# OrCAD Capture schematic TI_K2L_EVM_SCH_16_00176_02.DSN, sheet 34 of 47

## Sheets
34 PAGE44 : K2L_POWER SECTION 3: size C; title: LM26430, 12v -> CVVD1, 1v8, v85, 5v
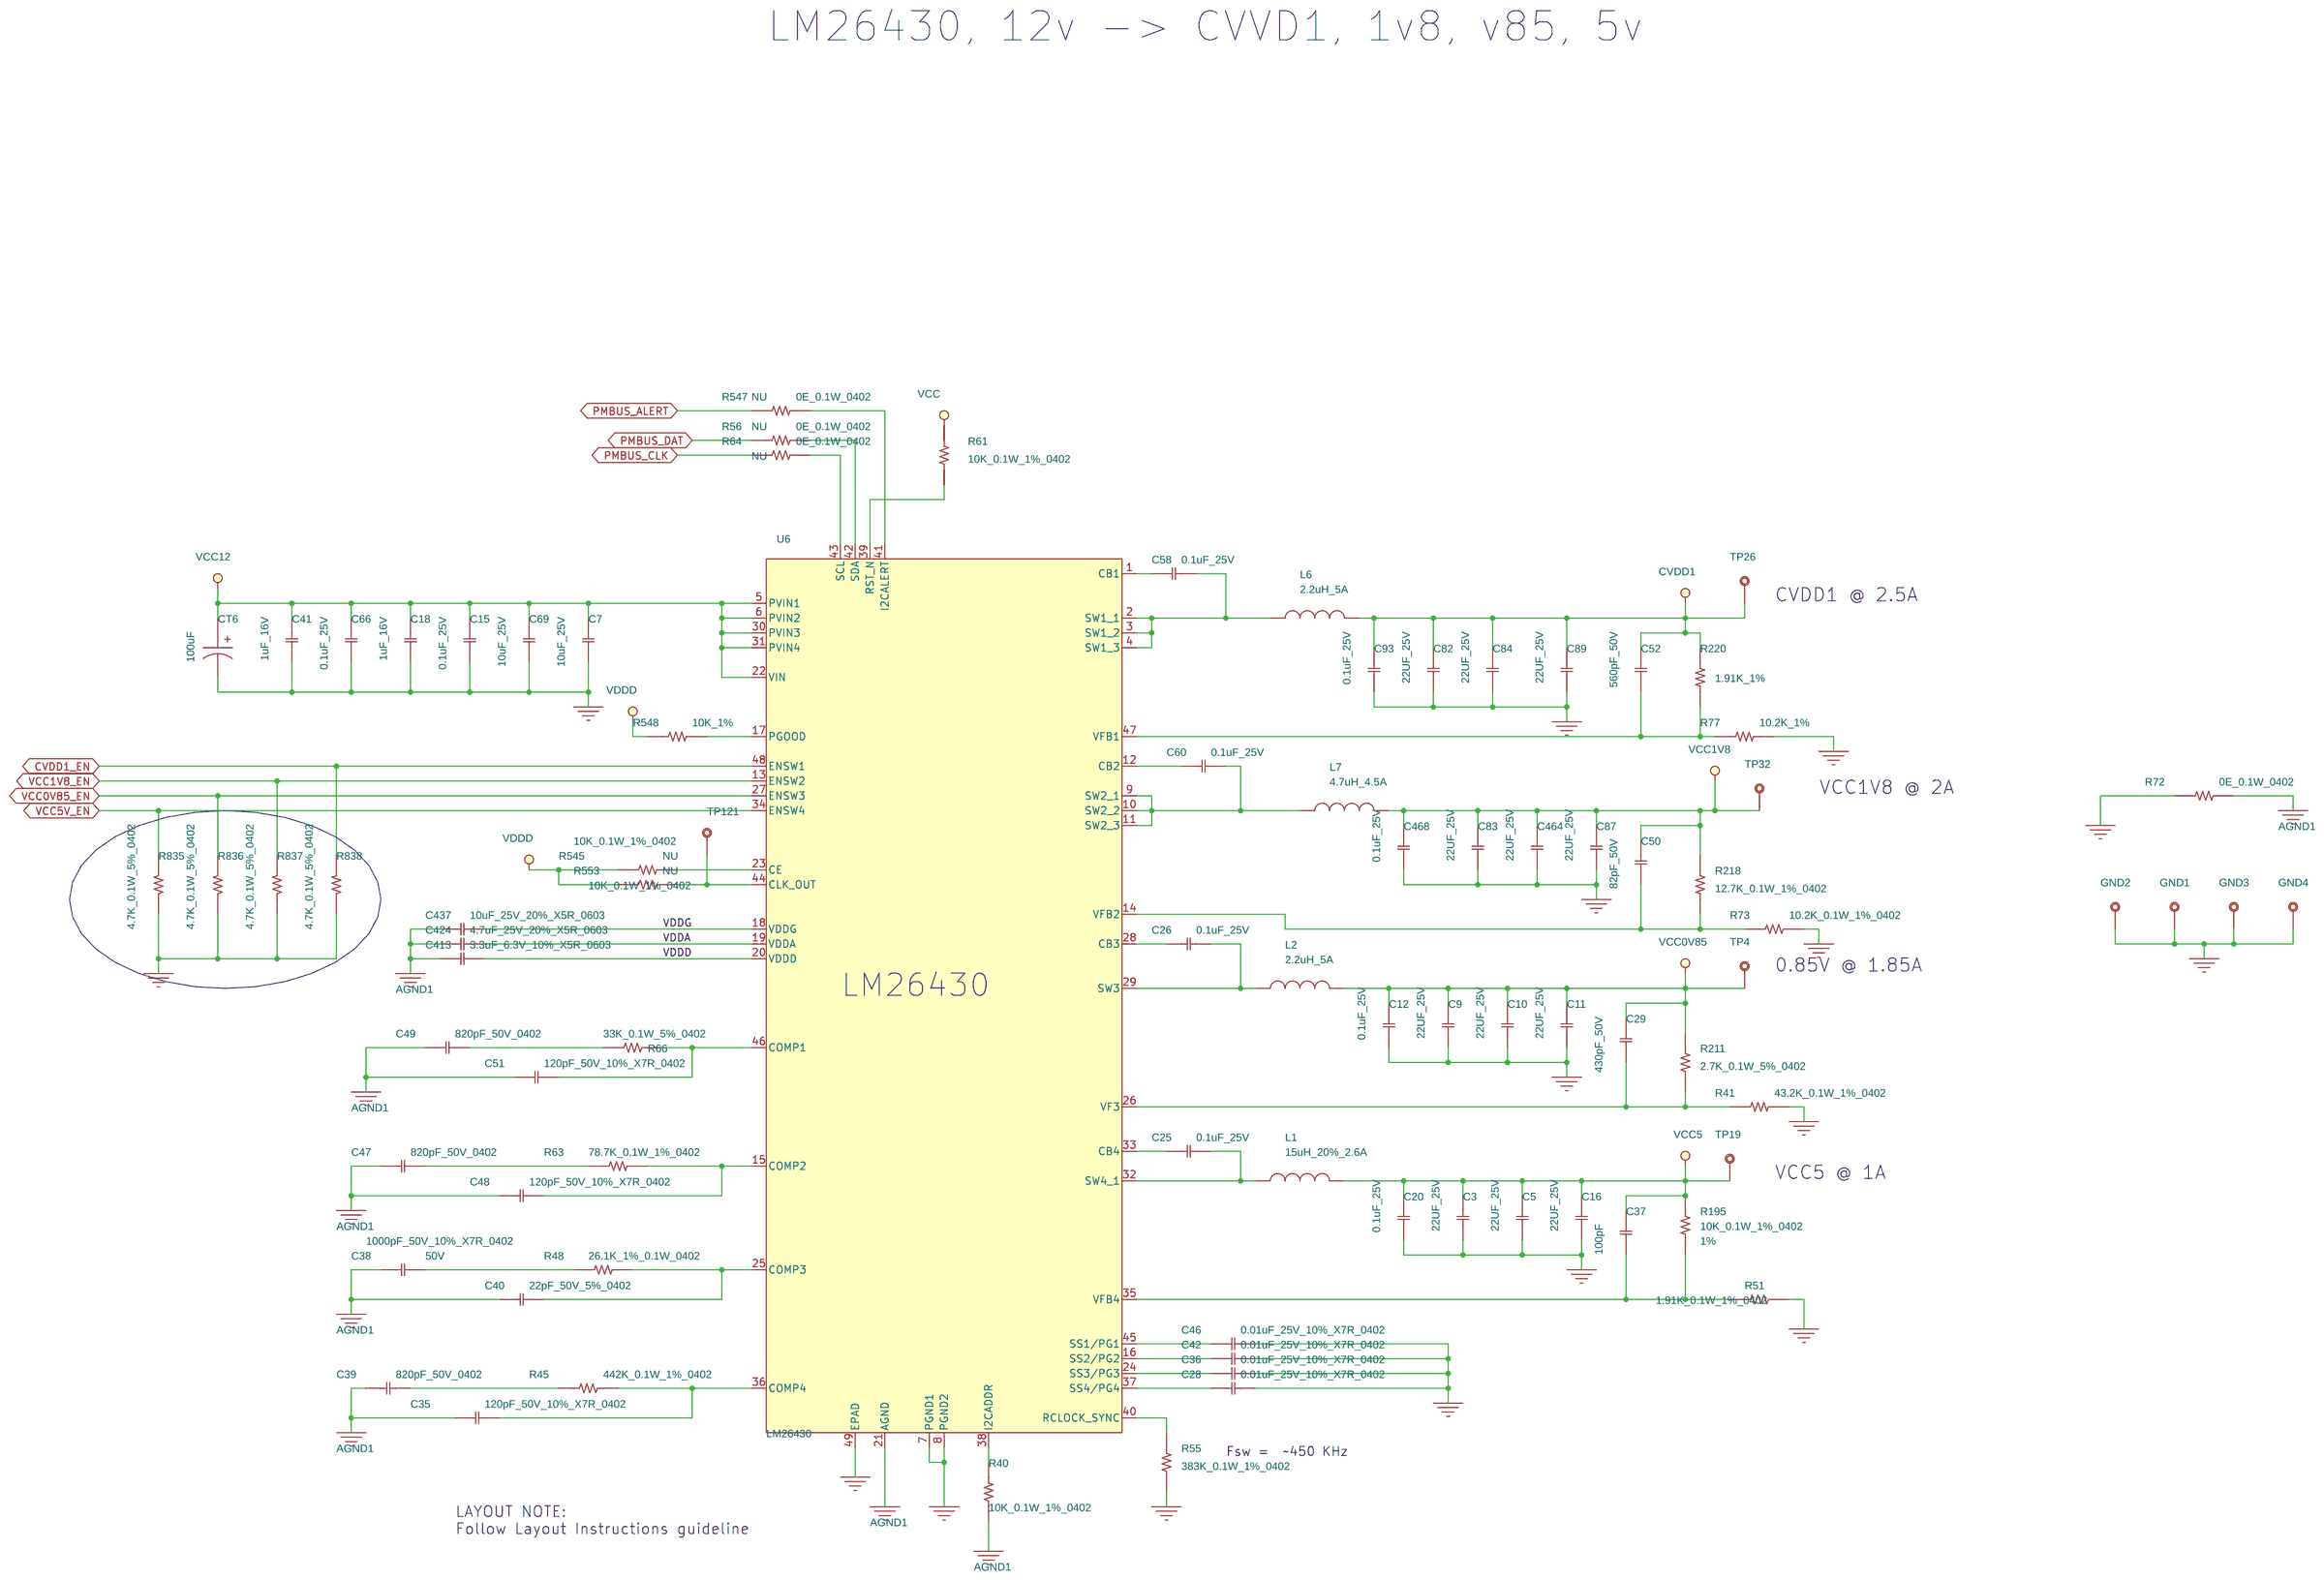
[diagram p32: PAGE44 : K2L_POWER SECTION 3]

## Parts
C3  22UF_25V  [C0805]
C5  22UF_25V  [C0805]
C7  10uF_25V  [C0603]
C9  22UF_25V  [C0805]
C10  22UF_25V  [C0805]
C11  22UF_25V  [C0805]
C12  0.1uF_25V  [C0402]
C15  0.1uF_25V  [C0402]
C16  22UF_25V  [C0805]
C18  1uF_16V  [C0402]
C20  0.1uF_25V  [C0402]
C25  0.1uF_25V  [C0402]
C26  0.1uF_25V  [C0402]
C28  0.01uF_25V_10%_X7R_0402  [C0402]
C29  430pF_50V  [C0402]
C35  120pF_50V_10%_X7R_0402  [C0402]
C36  0.01uF_25V_10%_X7R_0402  [C0402]
C37  100pF  [C0402]
C38  1000pF_50V_10%_X7R_0402  [C0402]
C39  820pF_50V_0402  [C0402]
C40  22pF_50V_5%_0402  [C0402]
C41  1uF_16V  [C0402]
C42  0.01uF_25V_10%_X7R_0402  [C0402]
C46  0.01uF_25V_10%_X7R_0402  [C0402]
C47  820pF_50V_0402  [C0402]
C48  120pF_50V_10%_X7R_0402  [C0402]
C49  820pF_50V_0402  [C0402]
C50  82pF_50V  [C0402]
C51  120pF_50V_10%_X7R_0402  [C0402]
C52  560pF_50V  [C0402]
C58  0.1uF_25V  [C0402]
C60  0.1uF_25V  [C0402]
C66  0.1uF_25V  [C0402]
C69  10uF_25V  [C0603]
C82  22UF_25V  [C0805]
C83  22UF_25V  [C0805]
C84  22UF_25V  [C0805]
C87  22UF_25V  [C0805]
C89  22UF_25V  [C0805]
C93  0.1uF_25V  [C0402]
C413  3.3uF_6.3V_10%_X5R_0603  [C0603]
C424  4.7uF_25V_20%_X5R_0603  [C0603]
C437  10uF_25V_20%_X5R_0603  [C0603]
C464  22UF_25V  [C0805]
C468  0.1uF_25V  [C0402]
CT6  100uF  [CT7343]
GND1  TP  [TP-S40]
GND2  TP  [TP-S40]
GND3  TP  [TP-S40]
GND4  TP  [TP-S40]
L1  15uH_20%_2.6A  [IND_ASPI-8040S-150M-T]
L2  2.2uH_5A  [IND_VLC5045T-2R2N]
L6  2.2uH_5A  [IND_VLC5045T-2R2N]
L7  4.7uH_4.5A  [IND_IHLP2020CZ]
R40  10K_0.1W_1%_0402  [R0402]
R41  43.2K_0.1W_1%_0402  [R0402]
R45  442K_0.1W_1%_0402  [R0402]
R48  26.1K_1%_0.1W_0402  [R0402]
R51  1.91K_0.1W_1%_0402  [R0402]
R55  383K_0.1W_1%_0402  [R0402]
R56  0E_0.1W_0402  [R0402]
R61  10K_0.1W_1%_0402  [R0402]
R63  78.7K_0.1W_1%_0402  [R0402]
R64  0E_0.1W_0402  [R0402]
R66  33K_0.1W_5%_0402  [R0402]
R72  0E_0.1W_0402  [R0402]
R73  10.2K_0.1W_1%_0402  [R0402]
R77  10.2K_1%  [R0402]
R195  10K_0.1W_1%_0402  [R0402]
R211  2.7K_0.1W_5%_0402  [R0402]
R218  12.7K_0.1W_1%_0402  [R0402]
R220  1.91K_1%  [R0402]
R545  10K_0.1W_1%_0402  [R0402]
R547  0E_0.1W_0402  [R0402]
R548  10K_1%  [R0402]
R553  10K_0.1W_1%_0402  [R0402]
R835  4.7K_0.1W_5%_0402  [R0402]
R836  4.7K_0.1W_5%_0402  [R0402]
R837  4.7K_0.1W_5%_0402  [R0402]
R838  4.7K_0.1W_5%_0402  [R0402]
TP4  TP  [TP-S40]
TP19  TP  [TP-S40]
TP26  TP  [TP-S40]
TP32  TP  [TP-S40]
TP121  TP  [TP-S40]
U6  LM26430  [QFN50P700X700X100-49N_C_EINF]

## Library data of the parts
C3 C5 C9-C11 C16 C82-C84 C87 C89 C464 = 11_C_0: CAP CER 22UF 25V 20% JB 0805; Alternate_Mfr: Samsung; Alternate_Partno: CL21A226MAQNNNE; Distributor_name: DIGIKEY; Distributor_part_number: 445-11475-2-ND; EIC Part#: 03_00586_01; Manufacture: TDK Corporation; Manufacture Part Number: C2012JB1E226M125AC; Manufacture(English): TDK Corporation; Manufacture_Part_Number: C2012JB1E226M125AC; Manufacturer: TDK Corporation; Manufacturer_Part_No: C2012JB1E226M125AC; Mfg: TDK Corporation; Mfg Part#: C2012JB1E226M125AC; Mfr_name: TDK Corporation; Mfr_part_number: C2012JB1E226M125AC; Oper. Temp. Range: -55C to 85C; Package: 0805; Price @ 1: 1.09000; Price @ 10K: 0.26265; Price @ 1K: 0.37647; ProcessType: SMT; RoHS: Yes; Tolerance: 10%; Vendor: DIGIKEY; Vendor Part#: 490-5527-1-ND; Vendor_Part_No: 03_00586_01; Voltage: 25V; eI Part#: 03_00586_01
C7 C69 = 11_C_12: CAP CER 10UF 25V 20% X5R 0603; Characteristic: <Characteristic>; Distributor_name: DIGIKEY; Distributor_part_number: 445-9015-1-ND; EIC Part#: 03_00609_01; Manufacture: TDK Corporation; Manufacture Part Number: C1608X5R1E106M080AC; Manufacture(English): TDK Corporation; Manufacture_Part_Number: C1608X5R1E106M080AC; Manufacturer: TDK Corporation; Manufacturer_Part_No: C1608X5R1E106M080AC; Mfg: TDK Corporation; Mfg Part#: C1608X5R1E106M080AC; Mfr_name: TDK Corporation; Mfr_part_number: C1608X5R1E106M080AC; Oper. Temp. Range: -55C to 85C; Package: 0603; Price @ 1: 0.60000; Price @ 10K: 0.19125; Price @ 1K: 0.19125; ProcessType: SMT; RoHS: Yes; Tolerance: 20%; Vendor: DIGIKEY; Vendor Part#: TDK Corporation; Vendor_Part_No: 445-9015-1-ND; Voltage: 25V; eI Part#: 03_00609_01
C12 C15 C20 C25 C26 C58 C60 C66 C93 C468 = 11_C_0: CAP CER 0.1UF 25V 10% X5R 0402; Alt Mfg: Taiyo Yuden; Distributor_name: DIGIKEY; Distributor_part_number: 445-4964-1-ND; EIC Part#: 03_00470_02; Manufacture: TDK Corporation; Manufacture Part Number: C1005X5R1E104K050BC; Manufacture(English): TDK Corporation; Manufacture_Part_Number: GRM155R61E104KA87D; Manufacturer: TDK Corporation; Manufacturer_Part_No: C1005X5R1E104K050BC; Mfg: Murata Electronics North America; Mfg Part#: 03_00470_02; Mfr_name: TDK Corporation; Mfr_part_number: C1005X5R1E104K050BC; Oper. Temp. Range: -55°C ~ 85°C; Package: 0402; Price @ 1: 0.10000; Price @ 1K: 0.00960; ProcessType: SMT; RoHS: Yes; Tolerance: 10%; Vendor: DIGIKEY; Vendor Part#: 445-4964-1-ND; Vendor_Part_No: 445-4964-1-ND; eI Part#: 03_00470_02
C18 C41 = 11_C_12: CAP CER 1UF 16V 10% X5R 0402; Characteristic: <Characteristic>; Distributor_name: DIGIKEY; Distributor_part_number: 445-4978-1-ND; EIC Part#: 03_00355_04; Manufacture: TDK Corporation; Manufacture Part Number: C1005X5R1C105K050BC; Manufacture(English): TDK Corporation; Manufacture_Part_Number: C1005X5R1C105K050BC; Manufacturer: TDK Corporation; Manufacturer_Part_No: C1005X5R1C105K050BC; Mfg: TDK Corporation; Mfg Part#: C1005X5R1C105K050BC; Mfr_name: TDK Corporation; Mfr_part_number: C1005X5R1C105K050BC; Oper. Temp. Range: -55C to 85C; Package: 0402; Price @ 1: 0.12000; Price @ 10K: 0.01600; Price @ 1K: 0.02200; ProcessType: SMT; RoHS: Yes; Tolerance: 10%; Vendor: DIGIKEY; Vendor Part#: 445-4978-1-ND; Vendor_Part_No: 445-4978-1-ND; Voltage: 25V; eI Part#: 03_00355_04
C28 C36 C42 C46 = 11_C_0: CAP CER 10000PF 25V 10% X7R 0402; Alt Mfg: Murata; Alt Mfg Part#: GRM155R71C103KA01D; Distributor_name: DIGIKEY; Distributor_part_number: 445-1260-1-ND; EIC Part#: 03_00029_04; Manufacture: TDK Corporation; Manufacture Part Number: C1005X7R1E103K; Manufacture(English): TDK Corporation; Manufacture_Part_Number: C1005X7R1E103K; Manufacturer: TDK Corporation; Manufacturer_Part_No: C1005X7R1E103K; Mfg: TDK Corporation; Mfg Part#: 03_00029_04; Mfr_name: TDK Corporation; Mfr_part_number: C1005X7R1E103K; Oper. Temp. Range: -55C to 125C; Package: 0402; Price @ 1: 0.10000; Price @ 10K: 0.00420; Price @ 1K: 0.00600; ProcessType: SMT; RoHS: Yes; Tolerance: 10%; Vendor: DIGIKEY; Vendor Part#: PCC103BQCT-ND; Vendor_Part_No: 445-1260-1-ND; eI Part#: 03_00029_04
C29 = 11_C_0: CAP CER 430PF 50V 2% NP0 0402; Distributor_name: DIGIKEY; Distributor_part_number: 490-6240-1-ND; EIC Part#: TBD; Manufacture: Murata; Manufacture Part Number: GRM1555C1H431GA01D; Manufacture(English): Murata; Manufacture_Part_Number: GRM1555C1H431GA01D; Manufacturer: Murata; Manufacturer_Part_No: GRM1555C1H431GA01D; Mfg Part#: TBD; Mfr_name: Murata; Mfr_part_number: GRM1555C1H431GA01D; Oper. Temp. Range: -55C to 125C; Package: 0402; ProcessType: SMT; RoHS: Yes; Tolerance: 10%; Vendor: DIGIKEY; Vendor Part#: 490-6240-1-ND; Vendor_Part_No: 490-6240-1-ND; Voltage: 50V; eI Part#: TBD
C35 C48 C51 = 11_C_0: CAP CER 120PF 10% 50V X7R 0402; Distributor_name: DIGIKEY; Distributor_part_number: 478-1090-1-ND; EIC Part#: 03_00049_03; Manufacture: AVX Corporation; Manufacture Part Number: 04025C121KAT2A; Manufacture(English): AVX Corporation; Manufacture_Part_Number: 04025C121KAT2A; Manufacturer: AVX Corporation; Manufacturer_Part_No: 04025C121KAT2A; Mfg: AVX Corporation; Mfg Part#: 03_00049_03; Mfr_name: AVX Corporation; Mfr_part_number: 04025C121KAT2A; Oper. Temp. Range: -55C to 125C; Package: 0402; Price @ 1: 0.12000; Price @ 10K: 0.01470; Price @ 1K: 0.02100; ProcessType: SMT; RoHS: Yes; Tolerance: 10%; Vendor: DIGIKEY; Vendor Part#: 478-1090-1-ND; Vendor_Part_No: 478-1090-1-ND; Voltage: 50V; eI Part#: 03_00049_03
C37 = 11_C_12: CAP CER 100PF 50V 5% NP0 0402; Characteristic: <Characteristic>; Distributor_name: DIGIKEY; Distributor_part_number: 490-5922-1-ND; EIC Part#: 03_00594_01; Manufacture: Murata; Manufacture Part Number: GRM1555C1H101JA01D; Manufacture(English): 490-5922-1-ND; Manufacture_Part_Number: GRM1555C1H101JA01D; Manufacturer: Murata; Manufacturer_Part_No: GRM1555C1H101JA01D; Mfg: Murata; Mfg Part#: GRM1555C1H101JA01D; Mfr_name: Murata; Mfr_part_number: GRM1555C1H101JA01D; Oper. Temp. Range: -55°C ~ 125°C; Package: 0402; Price @ 1: 0.10000; Price @ 10K: 0.00500; Price @ 1K: 0.00600; ProcessType: SMT; RoHS: Yes; Tolerance: 5%; Vendor: DIGIKEY; Vendor Part#: 490-5922-1-ND; Vendor_Part_No: 490-5922-1-ND; Voltage: 50V; eI Part#: 03_00594_01
C38 = 11_C_0: CAP CER 1000PF 50V 10% X7R 0402; Advansus_Part_Number: 11G232110214030; Characteristic: 50V; Distributor_name: DIGIKEY; Distributor_part_number: 1276-1493-1-ND; EIC Part#: 03_00591_01; Manufacture: Samsung; Manufacture Part Number: CL05B102KB5NFNC; Manufacture(English): Samsung; Manufacture_Part_Number: CL05B102KB5NFNC; Manufacturer: Samsung; Manufacturer_Part_No: CL05B102KB5NFNC; Mfg: Samsung; Mfg Part#: CL05B102KB5NFNC; Mfr_name: Samsung; Mfr_part_number: CL05B102KB5NFNC; Package: 0402; Part_Number: 1124510291; Price @ 1: 0.10000; Price @ 10K: 0.00216; Price @ 1K: 0.00309; ProcessType: SMT; Tolerance: 10%; Vendor: DIGIKEY; Vendor Part#: 1276-1493-1-ND; Vendor_Part_No: 1276-1493-1-ND; eI Part#: 03_00591_01
C39 C47 C49 = 11_C_12: CAP CER 820PF 50V 10% X7R 0402; Characteristic: 50V; Distributor_name: DIGIKEY; Distributor_part_number: 490-3250-1-ND; EIC Part#: 03_00285_02; Manufacture: Murata; Manufacture Part Number: GRM155R71H821KA01D; Manufacture(English): Murata; Manufacture_Part_Number: GRM155R71H821KA01D; Manufacturer: Murata; Manufacturer_Part_No: GRM155R71H821KA01D; Mfg: Murata Electronics North America; Mfg Part#: 03_00285_02; Mfr_name: Murata; Mfr_part_number: GRM155R71H821KA01D; Oper. Temp. Range: -55°C ~ 125°C; Package: 0402; Price @ 1: 0.10000; Price @ 10K: 0.00441; Price @ 1K: 0.00630; ProcessType: SMT; RoHS: Yes; Tolerance: 10%; Vendor: DIGIKEY; Vendor Part#: 490-1301-1-ND; Vendor_Part_No: 490-3250-1-ND; Voltage: 50V; eI Part#: 03_00285_02
C40 = 11_C_0: CAP CER 22PF 50V 0402 SMD; Alt Mfg: Yageo; Alt Mfg Part#: CC0402JRNPO9BN220; Alternate_Mfr: TDK Corporation; Alternate_Partno: C1005C0G1H220J050BA; Distributor_name: DIGIKEY; Distributor_part_number: PCC220CQCT-ND; EIC Part#: 03_00204_02; Manufacture: Panasonic - ECG; Manufacture Part Number: ECJ-0EC1H220J; Manufacture(English): Panasonic - ECG; Manufacture_Part_Number: ECJ-0EC1H220J; Manufacturer: Panasonic - ECG; Manufacturer_Part_No: ECJ-0EC1H220J; Mfg: Panasonic - ECG; Mfg Part#: 03_00204_02; Mfr_name: Panasonic - ECG; Mfr_part_number: ECJ-0EC1H220J; Oper. Temp. Range: -55C to 125C; Package: 0402; Price @ 1: TBD; Price @ 10K: TBD; Price @ 1K: TBD; ProcessType: SMT; RoHS: Yes; Tolerance: 5%; Vendor: DIGIKEY; Vendor Part#: PCC220CQCT-ND; Vendor_Part_No: PCC220CQCT-ND; eI Part#: 03_00204_02
C50 = 11_C_0: CAP CER 82PF 50V 5% NP0 0402; Distributor_name: DIGIKEY; Distributor_part_number: 490-5879-1-ND; EIC Part#: 03_00598_01; Manufacture: Murata; Manufacture Part Number: GRM1555C1H820JA01D; Manufacture(English): Murata; Manufacture_Part_Number: GRM1555C1H820JA01D; Manufacturer: Murata; Manufacturer_Part_No: GRM1555C1H820JA01D; Mfg: Murata Electronics North America; Mfg Part#: 03_00598_01; Mfr_name: Murata; Mfr_part_number: GRM1555C1H820JA01D; Oper. Temp. Range: -55C to 125C; Package: 0402; Price @ 1: 0.10000; Price @ 10K: 0.00368; Price @ 1K: 0.00525; ProcessType: SMT; RoHS: Yes; Tolerance: 10%; Vendor: DIGIKEY; Vendor Part#: 490-5879-1-ND; Vendor_Part_No: 490-5879-1-ND; Voltage: 50V; eI Part#: 03_00598_01
C52 = 11_C_12: CAP CER 560PF 50V 10% X7R 0402; Avalue_Part_Number: E1127556100H; Characteristic: 50V; Distributor_name: DIGIKEY; Distributor_part_number: 490-1301-1-ND; EIC Part#: 03_00189_02; Manufacture: Murata; Manufacture Part Number: GRM155R71H561KA01D; Manufacture(English): Murata; Manufacture_Part_Number: GRM155R71H561KA01D; Manufacturer: Murata; Manufacturer_Part_No: GRM155R71H561KA01D; Mfg: Murata Electronics North America; Mfg Part#: 03_00189_02; Mfr_name: Murata; Mfr_part_number: GRM155R71H561KA01D; Oper. Temp. Range: -55°C ~ 125°C; Package: 0402; Price @ 1: 0.10000; Price @ 10K: 0.00672; Price @ 1K: 0.00960; ProcessType: SMT; RoHS: Yes; Tolerance: 10%; Vendor: DIGIKEY; Vendor Part#: 490-1301-1-ND; Vendor_Part_No: 490-1301-1-ND; Voltage: 50V; eI Part#: 03_00189_02
C413 = 11_C_0: CAP CER 3.3UF 6.3V 10% X5R 0603; Distributor_name: DIGIKEY; Distributor_part_number: 445-5176-1-ND; EIC Part#: 03_00585_01; Manufacture: TDK Corporation; Manufacture Part Number: C1608X5R0J335K080AB; Manufacture(English): TDK Corporation; Manufacture_Part_Number: C1608X5R0J335K080AB; Manufacturer: TDK Corporation; Manufacturer_Part_No: C1608X5R0J335K080AB; Mfg: TDK Corporation; Mfg Part#: 03_00585_01; Mfr_name: TDK Corporation; Mfr_part_number: C1608X5R0J335K080AB; Oper. Temp. Range: -55C to 85C; Package: 0603; Price @ 1: 0.24000; Price @ 10K: 0.04625; Price @ 1K: 0.05875; ProcessType: SMT; RoHS: Yes; Tolerance: 10%; Vendor: DIGIKEY; Vendor Part#: 445-5176-1-ND; Vendor_Part_No: 445-5176-1-ND; Voltage: 6.3V; eI Part#: 03_00585_01
C424 = 11_C_0: CAP CER 4.7UF 25V 20% X5R 0603; Distributor_name: DIGIKEY; Distributor_part_number: 1276-1903-2-ND; EIC Part#: 03_00592_01; Manufacture: Samsung; Manufacture Part Number: CL10A475MA8NQNC; Manufacture(English): Samsung; Manufacture_Part_Number: CL10A475MA8NQNC; Manufacturer: Samsung; Manufacturer_Part_No: CL10A475MA8NQNC; Mfg: Samsung; Mfg Part#: CL10A475MA8NQNC; Mfr_name: Samsung; Mfr_part_number: CL10A475MA8NQNC; Oper. Temp. Range: -55C to 85C; Package: 0603; ProcessType: SMT; RoHS: Yes; Tolerance: 10%; Vendor: DIGIKEY; Vendor Part#: 1276-1903-2-ND; Vendor_Part_No: 1276-1903-2-ND; Voltage: 25V; eI Part#: 03_00592_01
C437 = 11_C_0: CAP CER 10UF 25V 20% X5R 0603; Distributor_name: DIGIKEY; Distributor_part_number: 445-9015-1-ND; EIC Part#: 03_00609_01; Manufacture: TDK Corporation; Manufacture Part Number: C1608X5R1E106M080AC; Manufacture(English): TDK Corporation; Manufacture_Part_Number: C1608X5R1E106M080AC; Manufacturer: TDK Corporation; Manufacturer_Part_No: C1608X5R1E106M080AC; Mfg: TDK Corporation; Mfg Part#: C1608X5R1E106M080AC; Mfr_name: TDK Corporation; Mfr_part_number: C1608X5R1E106M080AC; Oper. Temp. Range: -55C to 85C; Package: 0603; Price @ 1: 0.60000; Price @ 10K: 0.19125; Price @ 1K: 0.19125; ProcessType: SMT; RoHS: Yes; Tolerance: 20%; Vendor: DIGIKEY; Vendor Part#: TDK Corporation; Vendor_Part_No: 445-9015-1-ND; Voltage: 25V; eI Part#: 03_00609_01
CT6 = CAP_POL: CAP TANT 100UF 20V 10% 2917; Distributor_name: DIGIKEY; Distributor_part_number: 718-1774-1-ND; EIC Part#: 03_00602_01; Manufacture: Vishay; Manufacture Part Number: TR3D107K020C0080; Manufacture(English): Vishay Dale; Manufacture_Part_Number: TR3D107K020C0080; Manufacturer: Vishay Dale; Manufacturer_Part_No: TR3D107K020C0080; Mfg: Vishay Dale; Mfg Part#: TR3D107K020C0080; Mfr_name: Vishay Dale; Mfr_part_number: TR3D107K020C0080; Oper. Temp. Range: -40°C ~ 85°C; Package: 7343; RoHS: Yes; Vendor: DIGIKEY; Vendor Part#: 718-1774-1-ND; Vendor_Part_No: 718-1774-1-ND; Voltage: 25V; eI Part#: 03_00602_01
GND1-GND4 TP4 TP19 TP26 TP32 TP121 = 00_TP-S40_0: TEST PAD TP; Distributor_name: NA; Distributor_part_number: NA; EIC Part#: NA; Manufacture: NA; Manufacture Part Number: NA; Manufacture(English): NA; Manufacture_Part_Number: NA; Manufacturer: NA; Manufacturer_Part_No: NA; Mfg: NA; Mfg Part#: NA; Mfr_name: NA; Mfr_part_number: NA; Oper. Temp. Range: --NA--; Package: --NA--; Price @ 1: NA; Price @ 10K: NA; Price @ 1K: NA; ProcessType: SMT; RoHS: Yes; Vendor: NA; Vendor Part#: --NA--; Vendor_Part_No: NA; eI Part#: NA
L1 = DISC_INDUCTOR: INDUCTOR POWER 15UH 20% SMD; Distributor_name: DIGIKEY; Distributor_part_number: ASPI-8040S-150M-TCT-ND; EIC Part#: TBD; Manufacture: Abracon Corporation; Manufacture Part Number: ASPI-8040S-150M-T; Manufacture(English): Abracon Corporation; Manufacture_Part_Number: ASPI-8040S-150M-T; Manufacturer: Abracon Corporation; Manufacturer_Part_No: ASPI-8040S-150M-T; Mfg: Abracon Corporation; Mfg Part#: TBD; Mfr_name: Abracon Corporation; Mfr_part_number: ASPI-8040S-150M-T; Price @ 1: 0.73000; Price @ 10K: 0.43876; Price @ 1K: 0.29250; RoHS: Yes; RoHS Compliant?: RoHS Compliant; Tolerance: 20%; Vendor: DIGIKEY; Vendor Part#: ASPI-8040S-150M-TCT-ND; Vendor_Part_No: ASPI-8040S-150M-TCT-ND; eI Part#: TBD
L2 L6 = DISC_INDUCTOR: INDUCTOR POWER 2.2UH 5.0A SMD; Distributor_name: DIGIKEY; Distributor_part_number: 445-6523-1-ND; EIC Part#: 04_00346_01; Manufacture: TDK Corporation; Manufacture Part Number: VLC5045T-2R2N; Manufacture(English): TDK Corporation; Manufacture_Part_Number: VLC5045T-2R2N; Manufacturer: TDK Corporation; Manufacturer_Part_No: VLC5045T-2R2N; Mfg Part#: VLC5045T-2R2N; Mfr_name: TDK Corporation; Mfr_part_number: VLC5045T-2R2N; Price @ 1: 0.48000; Price @ 10K: 0.13664; Price @ 1K: 0.16800; RoHS Compliant?: RoHS Compliant; Vendor: DIGIKEY; Vendor_Part_No: 445-6523-1-ND; eI Part#: 04_00408_01
L7 = DISC_INDUCTOR: INDUCTOR POWER 4.7UH 4.5A SMD; Distributor_name: DIGIKEY; Distributor_part_number: 541-1238-1-ND; EIC Part#: 04_00380_01; Manufacture: Vishay Dale; Manufacture Part Number: IHLP2020CZER4R7M11; Manufacture(English): Vishay Dale; Manufacture_Part_Number: IHLP2020CZER4R7M11; Manufacturer: Vishay Dale; Manufacturer_Part_No: IHLP2020CZER4R7M11; Mfg Part#: 04_00380_01; Mfr_name: Vishay Dale; Mfr_part_number: IHLP2020CZER4R7M11; Price @ 1: 2.40000; Price @ 10K: 0.99200; Price @ 1K: 1.31200; RoHS Compliant?: RoHS Compliant; Vendor: DIGIKEY; Vendor_Part_No: 541-1238-1-ND; eI Part#: 04_00380_01
R40 R61 R548 = 10_R_0: RES 10K OHM 1/10W 1% 0402 SMD; Alt Mfg: Yageo; Alt Mfg Part#: RC0402FR-0710KL; Distributor_name: DIGIKEY; Distributor_part_number: P10.0KLCT-ND; EIC Part#: 02_00027_01; Manufacture: Panasonic - ECG; Manufacture Part Number: ERJ-2RKF1002X; Manufacture(English): Panasonic - ECG; Manufacture_Part_Number: ERJ-2RKF1002X; Manufacturer: Panasonic - ECG; Manufacturer_Part_No: ERJ-2RKF1002X; Mfg Part#: 02_00027_01; Mfr_name: Panasonic - ECG; Mfr_part_number: ERJ-2RKF1002X; Oper. Temp. Range: -55C ~ 125C; Package: 0402; Price @ 1: 0.10000; Price @ 10K: 0.00347; Price @ 1K: 0.00672; ProcessType: SMT; Remark: Alt part is 1/16W; RoHS: Yes; Tolerance: 1%; Vendor: DIGIKEY; Vendor Part#: P10.0KLCT-ND; Vendor_Part_No: P10.0KLCT-ND; eI Part#: 02_00027_01
R41 = 10_R_0: RES 43.2K OHM 1/10W 1% 0402 SMD; Distributor_name: DIGIKEY; Distributor_part_number: P43.2KLCT-ND; EIC Part#: 02_00764_01; Manufacture: Panasonic - ECG; Manufacture Part Number: ERJ-2RKF4322X; Manufacture(English): Panasonic - ECG; Manufacture_Part_Number: ERJ-2RKF4322X; Manufacturer: Panasonic - ECG; Manufacturer_Part_No: ERJ-2RKF4322X; Mfg Part#: 02_00764_01; Mfr_name: Panasonic - ECG; Mfr_part_number: ERJ-2RKF4322X; Oper. Temp. Range: -55C ~ 125C; Package: 0402; ProcessType: SMT; RoHS: Yes; Tolerance: 1%; Vendor: DIGIKEY; Vendor Part#: P43.2KLCT-ND; Vendor_Part_No: P43.2KLCT-ND; eI Part#: 02_00024_01
R45 = 10_R_0: RES 442K OHM 1/16W 1% 0402 SMD; Distributor_name: DIGIKEY; Distributor_part_number: P442KLCT-ND; EIC Part#: 02_00308_01; Manufacture: Panasonic - ECG; Manufacture Part Number: ERJ-2RKF4423X; Manufacture(English): Panasonic - ECG; Manufacture_Part_Number: ERJ-2RKF4423X; Manufacturer: Panasonic - ECG; Manufacturer_Part_No: ERJ-2RKF4423X; Mfg Part#: 02_00308_01; Mfr_name: Panasonic - ECG; Mfr_part_number: ERJ-2RKF4423X; Oper. Temp. Range: ±100ppm/°C; Package: 0402; ProcessType: SMT; RoHS: Yes; Tolerance: 1%; Vendor: DIGIKEY; Vendor Part#: 541-442KLCT-ND; Vendor_Part_No: P442KLCT-ND; eI Part#: 02_00483_01
R48 = 10_R_0: RES 26.1K OHM 1/10W 1% 0402 SMD; Distributor_name: DIGIKEY; Distributor_part_number: TBD; EIC Part#: TBD; Manufacture: Panasonic - ECG; Manufacture Part Number: ERJ-2RKF2612X; Manufacture(English): Panasonic - ECG; Manufacture_Part_Number: ERJ-2RKF2612X; Manufacturer: Panasonic - ECG; Manufacturer_Part_No: ERJ-2RKF2612X; Mfg Part#: TBD; Mfr_name: Panasonic - ECG; Mfr_part_number: ERJ-2RKF2612X; Oper. Temp. Range: -55C ~ 125C; Package: 0402; ProcessType: SMT; Remark: Alt part is 1/10W; RoHS: Yes; Tolerance: 1%; Vendor: DIGIKEY; Vendor Part#: TBD; Vendor_Part_No: TBD; eI Part#: TBD
R51 R220 = 10_R_0: RES 1.91K OHM 1/10W 1% 0402 SMD; Alt Mfg: Yageo; Alt Mfg Part#: RC0402FR-0710KL; Distributor_name: DIGIKEY; Distributor_part_number: P1.91KLCT-ND; EIC Part#: 02_00297_02; Manufacture: Panasonic - ECG; Manufacture Part Number: ERJ-2RKF1911X; Manufacture(English): Panasonic - ECG; Manufacture_Part_Number: ERJ-2RKF1911X; Manufacturer: Panasonic - ECG; Manufacturer_Part_No: ERJ-2RKF1911X; Mfg Part#: 02_00297_02; Mfr_name: Panasonic - ECG; Mfr_part_number: ERJ-2RKF1911X; Oper. Temp. Range: -55C ~ 125C; Package: 0402; ProcessType: SMT; Remark: Alt part is 1/10W; RoHS: Yes; Tolerance: 1%; Vendor: DIGIKEY; Vendor Part#: P1.91KLDKR-ND; Vendor_Part_No: P1.91KLCT-ND; eI Part#: 02_00483_01
R55 = 10_R_0: RES 383K OHM 1/10W 1% 0402 SMD; Distributor_name: DIGIKEY; Distributor_part_number: P383KLCT-ND; EIC Part#: TBD; Manufacture: Panasonic - ECG; Manufacture Part Number: ERJ-2RKF3833X; Manufacture(English): Panasonic - ECG; Manufacturer: Panasonic - ECG; Manufacturer_Part_No: ERJ-2RKF3833X; Mfg Part#: TBD; Mfr_name: Panasonic - ECG; Mfr_part_number: ERJ-2RKF3833X; Oper. Temp. Range: -55C ~ 125C; Package: 0402; ProcessType: SMT; Remark: Alt part is 1/10W; RoHS: Yes; Tolerance: 1%; Vendor: DIGIKEY; Vendor_Part_No: P383KLCT-ND; eI Part#: 02_00027_01
R56 R64 R547 = 10_R_0: RES 0.0 OHM 1/10W JUMP 0402 SMD; Alt Mfg: Yageo; Distributor_name: DIGIKEY; Distributor_part_number: P0.0JCT-ND; EIC Part#: 02_00019_01; Manufacture: Panasonic - ECG; Manufacture Part Number: ERJ-2GE0R00X; Manufacture(English): Panasonic - ECG; Manufacture_Part_Number: ERJ-2GE0R00X; Manufacturer: Panasonic - ECG; Manufacturer_Part_No: ERJ-2GE0R00X; Mfg Part#: 02_00019_01; Mfr_name: Panasonic - ECG; Mfr_part_number: ERJ-2GE0R00X; Mounting: NU; Mounting Status: NU; Mounting_Status: NU; Oper. Temp. Range: -55C to 125C; Package: 0402; ProcessType: SMT; Remark: Alt part is 1/16W; RoHS: Yes; Tolerance: 5%; Vendor: DIGIKEY; Vendor Part#: P0.0JCT-ND; Vendor_Part_No: P0.0JCT-ND; eI Part#: 02_00019_01
R63 = 10_R_0: RES 78.7K OHM 1/10W 1% 0402 SMD; Distributor_name: DIGIKEY; Distributor_part_number: P78.7KLCT-ND; EIC Part#: 02_00361_01; Manufacture: Panasonic - ECG; Manufacture Part Number: ERJ-2RKF7872X; Manufacture(English): Panasonic - ECG; Manufacture_Part_Number: ERJ-2RKF7872X; Manufacturer: Panasonic - ECG; Manufacturer_Part_No: ERJ-2RKF7872X; Mfg Part#: 02_00361_01; Mfr_name: Panasonic - ECG; Mfr_part_number: ERJ-2RKF7872X; Oper. Temp. Range: -55C ~ 125C; Package: 0402; ProcessType: SMT; Remark: Alt part is 1/10W; RoHS: Yes; Tolerance: 1%; Vendor: DIGIKEY; Vendor Part#: P78.7KLCT-ND; Vendor_Part_No: P78.7KLCT-ND; eI Part#: 02_00122_02
R66 = 10_R_0: RES 33K OHM 1/10W 5% 0402 SMD; Distributor_name: DIGIKEY; Distributor_part_number: P33KJCT-ND; EIC Part#: 02_00356_01; Manufacture: Panasonic - ECG; Manufacture Part Number: ERJ-2GEJ333X; Manufacture(English): Panasonic - ECG; Manufacture_Part_Number: ERJ-2GEJ333X; Manufacturer: Panasonic - ECG; Manufacturer_Part_No: ERJ-2GEJ333X; Mfg Part#: 02_00356_01; Mfr_name: Panasonic - ECG; Mfr_part_number: ERJ-2GEJ333X; Oper. Temp. Range: -55C ~ 125C; Package: 0402; ProcessType: SMT; Remark: Alt part is 1/10W; RoHS: Yes; Tolerance: 5%; Vendor: DIGIKEY; Vendor Part#: P33KJCT-ND; Vendor_Part_No: P33KJCT-ND; eI Part#: 02_00483_01
R72 = 10_R_0: RES 0.0 OHM 1/10W JUMP 0402 SMD; Alt Mfg: Yageo; Distributor_name: DIGIKEY; Distributor_part_number: P0.0JCT-ND; EIC Part#: 02_00019_01; Manufacture: Panasonic - ECG; Manufacture Part Number: ERJ-2GE0R00X; Manufacture(English): Panasonic - ECG; Manufacture_Part_Number: ERJ-2GE0R00X; Manufacturer: Panasonic - ECG; Manufacturer_Part_No: ERJ-2GE0R00X; Mfg Part#: 02_00019_01; Mfr_name: Panasonic - ECG; Mfr_part_number: ERJ-2GE0R00X; Oper. Temp. Range: -55C to 125C; Package: 0402; ProcessType: SMT; Remark: Alt part is 1/16W; RoHS: Yes; Tolerance: 5%; Vendor: DIGIKEY; Vendor Part#: P0.0JCT-ND; Vendor_Part_No: P0.0JCT-ND; eI Part#: 02_00019_01
R73 = 10_R_0: RES 10.2K OHM 1/10W 1% 0402 SMD; Alt Mfg: Yageo; Alt Mfg Part#: RC0402FR-0710KL; Distributor_name: ELEMENT14; Distributor_part_number: 2282634; EIC Part#: 02_00720_01; Manufacture: Panasonic - ECG; Manufacture Part Number: ERJ-2RKF1022X; Manufacture(English): Panasonic - ECG; Manufacture_Part_Number: ERJ-2RKF1022X; Manufacturer: Panasonic - ECG; Manufacturer_Part_No: ERJ-2RKF1022X; Mfg Part#: 02_00720_01; Mfr_name: Panasonic - ECG; Mfr_part_number: ERJ-2RKF1022X; Oper. Temp. Range: -55C ~ 125C; Package: 0402; ProcessType: SMT; Remark: Alt part is 1/10W; RoHS: Yes; Tolerance: 1%; Vendor: ELEMENT14; Vendor Part#: P10.2KLCT-ND; Vendor_Part_No: 2282634; eI Part#: 02_00483_01
R77 = 10_R_0: RES 10.2K OHM 1/10W 1% 0402 SMD; Alt Mfg: Yageo; Alt Mfg Part#: RC0402FR-0710KL; Distributor_name: ELEMENT14; Distributor_part_number: 2282634; EIC Part#: 02_00720_01; Manufacture: Panasonic - ECG; Manufacture Part Number: ERJ-2RKF1022X; Manufacture(English): Panasonic - ECG; Manufacture_Part_Number: ERJ-2RKF1022X; Manufacturer: Panasonic - ECG; Manufacturer_Part_No: ERJ-2RKF1022X; Mfg Part#: 02_00720_01; Mfr_name: Panasonic - ECG; Mfr_part_number: ERJ-2RKF1022X; Oper. Temp. Range: -55C ~ 125C; Package: 0402; ProcessType: SMT; Remark: Alt part is 1/10W; RoHS: Yes; Tolerance: 1%; Vendor: ELEMENT14; Vendor Part#: P10.2KLCT-ND; Vendor_Part_No: 2282634; eI Part#: 02_00558_01
R195 = 10_R_0: RES 10K OHM 1/10W 1% 0402 SMD; Characteristic: 1%; Distributor_name: DIGIKEY; Distributor_part_number: P10.0KLCT-ND; EIC Part#: 02_00027_01; Manufacture: Panasonic - ECG; Manufacture Part Number: ERJ-2RKF1002X; Manufacture(English): Panasonic - ECG; Manufacture_Part_Number: ERJ-2RKF1002X; Manufacturer: Panasonic - ECG; Manufacturer_Part_No: ERJ-2RKF1002X; Mfg: PANASONIC ELECTRONIC COMPONENTS (VA); Mfg Part#: 02_00027_01; Mfr_name: Panasonic - ECG; Mfr_part_number: ERJ-2RKF1002X; Package: 0402; Part_Number: 105A50103A; Price @ 1: 0.10000; Price @ 10K: 0.00347; Price @ 1K: 0.00672; ProcessType: SMT; Tolerance: 1%; Vendor: DIGIKEY; Vendor_Part_No: P10.0KLCT-ND; eI Part#: 02_00027_01
R211 = 10_R_0: RES 2.7K OHM 1/10W 5% 0402 SMD; Alt Mfg: Yageo; Alt Mfg Part#: RC0402FR-0710KL; Distributor_name: DIGIKEY; Distributor_part_number: P2.7KJCT-ND; EIC Part#: 02_00280_01; Manufacture: Panasonic - ECG; Manufacture Part Number: ERJ-2GEJ272X; Manufacture(English): Panasonic - ECG; Manufacture_Part_Number: ERJ-2GEJ272X; Manufacturer: Panasonic - ECG; Manufacturer_Part_No: ERJ-2GEJ272X; Mfg Part#: 02_00280_01; Mfr_name: Panasonic - ECG; Mfr_part_number: ERJ-2GEJ272X; Oper. Temp. Range: -55C ~ 125C; Package: 0402; ProcessType: SMT; Remark: Alt part is 1/10W; RoHS: Yes; Tolerance: 5%; Vendor: DIGIKEY; Vendor Part#: P2.7KJCT-ND; Vendor_Part_No: P2.7KJCT-ND; eI Part#: 02_00122_02
R218 = 10_R_0: RES 12.7K OHM 1/10W 1% 0402 SMD; Alt Mfg: Yageo; Alt Mfg Part#: RC0402FR-0710KL; Distributor_name: DIGIKEY; Distributor_part_number: P12.7KLCT-ND; EIC Part#: 02_00480_01; Manufacture: Panasonic - ECG; Manufacture Part Number: ERJ-2RKF1272X; Manufacture(English): Panasonic - ECG; Manufacture_Part_Number: ERJ-2RKF1272X; Manufacturer: Panasonic - ECG; Manufacturer_Part_No: ERJ-2RKF1272X; Mfg Part#: 02_00480_01; Mfr_name: Panasonic - ECG; Mfr_part_number: ERJ-2RKF1272X; Oper. Temp. Range: -55C ~ 125C; Package: 0402; ProcessType: SMT; Remark: Alt part is 1/10W; RoHS: Yes; Tolerance: 1%; Vendor: DIGIKEY; Vendor Part#: P12.7KLCT-ND; Vendor_Part_No: P12.7KLCT-ND; eI Part#: 02_00483_01
R545 R553 = 10_R_0: RES 10K OHM 1/10W 1% 0402 SMD; Alt Mfg: Yageo; Alt Mfg Part#: RC0402FR-0710KL; Distributor_name: DIGIKEY; Distributor_part_number: P10.0KLCT-ND; EIC Part#: 02_00027_01; Manufacture: Panasonic - ECG; Manufacture Part Number: ERJ-2RKF1002X; Manufacture(English): Panasonic - ECG; Manufacture_Part_Number: ERJ-2RKF1002X; Manufacturer: Panasonic - ECG; Manufacturer_Part_No: ERJ-2RKF1002X; Mfg Part#: 02_00027_01; Mfr_name: Panasonic - ECG; Mfr_part_number: ERJ-2RKF1002X; Mounting: NU; Mounting Status: NU; Mounting_Status: NU; Oper. Temp. Range: -55C ~ 125C; Package: 0402; Price @ 1: 0.10000; Price @ 10K: 0.00347; Price @ 1K: 0.00672; ProcessType: SMT; Remark: Alt part is 1/16W; RoHS: Yes; Tolerance: 1%; Vendor: DIGIKEY; Vendor Part#: P10.0KLCT-ND; Vendor_Part_No: P10.0KLCT-ND; eI Part#: 02_00027_01
R835-R838 = 10_R_0: RES 4.7K OHM 1/10W 5% 0402 SMD; Distributor_name: DIGIKEY; Distributor_part_number: P4.7KJCT-ND; EIC Part#: 02_00023_01; Manufacture: Panasonic - ECG; Manufacture Part Number: ERJ-2GEJ472X; Manufacture(English): Panasonic - ECG; Manufacture_Part_Number: ERJ-2GEJ472X; Manufacturer: Panasonic - ECG; Manufacturer_Part_No: ERJ-2GEJ472X; Mfg: Panasonic Electronic Components; Mfg Part#: 02_00266_01; Mfr_name: Panasonic - ECG; Mfr_part_number: ERJ-2GEJ472X; Price @ 1: 0.10000; Price @ 10K: 0.00347; Price @ 1K: 0.00672; Vendor: DIGIKEY; Vendor_Part_No: P4.7KJCT-ND; eI Part#: 02_00023_01
U6 = LM26430_2: QUAD SWITCHER, PMU WITH PMBus AND INTEGRATED SEQUENCING; Distributor_name: TBD; Distributor_part_number: TBD; EIC Part#: 01_01134_01; Manufacture: TI; Manufacture(English): TI; Manufacturer: TI; Mfg: TI; Mfg Part#: 01_01134_01; Mfr_name: TI; Price @ 1: TBD; Price @ 10K: TBD; Price @ 1K: TBD; RoHS: Yes; Vendor: TBD; Vendor_Part_No: TBD; eI Part#: 01_01134_01

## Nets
AGND1: C35.2 C38.1 C39.1 C40.2 C47.1 C48.2 C49.1 C51.2 C413.1 C424.1 C437.1 R40.1 R72.2 U6.21(AGND)
GND: C3.2 C5.2 C7.2 C9.2 C10.2 C11.2 C12.2 C15.2 C16.2 C18.2 C20.2 C28.2 C36.2 C41.2 C42.2 C46.2 C66.2 C69.2 C82.2 C83.2 C84.2 C87.2 C89.2 C93.2 C464.2 C468.2 CT6.2(Negative) GND1.1 GND2.1 GND3.1 GND4.1 R41.1 R51.2 R55.2 R72.1 R73.1 R77.1 R835.1 R836.1 R837.1 R838.1 U6.7(PGND1) U6.8(PGND2) U6.49(EPAD) ; also on sheet 1 2 3 4 5 6 8 10 11 12 13 14 15 16 17 18 19 20 21 22 24 25 26 27 28 29 33 35 36 37 40 41 42 43 45 46 47
VCC0V85: C9.1 C10.1 C11.1 C12.1 C29.2 L2.2 R211.1 TP4.1 ; also on sheet 33 37
VCC0V85_EN: R836.2 U6.27(ENSW3) ; also on sheet 37
VCC1V8: C50.2 C83.1 C87.1 C464.1 C468.1 L7.2 R218.1 TP32.1 ; also on sheet 2 6 8 11 19 21 22 25 26 27 29 33 36 37 41
VCC1V8_EN: R837.2 U6.13(ENSW2) ; also on sheet 37
VCC5: C3.1 C5.1 C16.1 C20.1 C37.2 L1.2 R195.1 TP19.1 ; also on sheet 8 26 37
VCC5V_EN: R835.2 U6.34(ENSW4) ; also on sheet 37
VCC12: C7.1 C15.1 C18.1 C41.1 C66.1 C69.1 CT6.1(Positive) U6.5(PVIN1) U6.6(PVIN2) U6.22(VIN) U6.30(PVIN3) U6.31(PVIN4) ; also on sheet 25 33 35
VDDA: C424.2 U6.19(VDDA)
VDDD: C413.2 R61.2 R545.1 R548.1 R553.1 U6.20(VDDD)
VDDG: C437.2 U6.18(VDDG)
CVDD1: C52.2 C82.1 C84.1 C89.1 C93.1 L6.2 R220.1 TP26.1 ; also on sheet 36 37
CVDD1_EN: R838.2 U6.48(ENSW1) ; also on sheet 37
PMBUS_ALERT: R547.1 ; also on sheet 5 6 35 37
PMBUS_CLK: R64.1 ; also on sheet 35 37
PMBUS_DAT: R56.1 ; also on sheet 35 37
N18343372: C42.1 U6.16(SS2/PG2)
N18343394: C36.1 U6.24(SS3/PG3)
N18343412: C28.1 U6.37(SS4/PG4)
N18343418: R61.1 U6.39(RST_N)
N18343619: R55.1 U6.40(RCLOCK_SYNC)
N18343644: C52.1 R77.2 R220.2 U6.47(VFB1)
N18343806: C46.1 U6.45(SS1/PG1)
N18343833: C51.1 R66.1 U6.46(COMP1)
N18343849: C49.2 R66.2
N18343902: C58.2 L6.1 U6.2(SW1_1) U6.3(SW1_2) U6.4(SW1_3)
N18343996: R64.2 U6.43(SCL)
N18344000: R547.2 U6.41(I2CALERT)
N18344032: C58.1 U6.1(CB1)
N18344044: R56.2 U6.42(SDA)
N18344216: R545.2 U6.23(CE)
N18344411: R548.2 U6.17(PGOOD)
N18344661: R553.2 TP121.1 U6.44(CLK_OUT)
N18364719: C35.1 R45.1 U6.36(COMP4)
N18364727: C39.2 R45.2
N18365104: C37.1 R51.1 R195.2 U6.35(VFB4)
N18365126: C25.2 L1.1 U6.32(SW4_1)
N18365132: C25.1 U6.33(CB4)
N18365826: C50.1 R73.2 R218.2 U6.14(VFB2)
N18365848: C60.2 L7.1 U6.9(SW2_1) U6.10(SW2_2) U6.11(SW2_3)
N18365850: C60.1 U6.12(CB2)
N18366146: C47.2 R63.2
N18366148: C48.1 R63.1 U6.15(COMP2)
N18366362: C38.2 R48.2
N18366364: C40.1 R48.1 U6.25(COMP3)
N18366737: C26.2 L2.1 U6.29(SW3)
N18366739: C29.1 R41.2 R211.2 U6.26(VF3)
N18366765: C26.1 U6.28(CB3)
N20300053: R40.2 U6.38(I2CADDR)

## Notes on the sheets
sheet 34
- LM26430, 12v -> CVVD1, 1v8, v85, 5v
- CVDD1 @ 2.5A
- VCC1V8 @ 2A
- 0.85V @ 1.85A
- LM26430
- VCC5 @ 1A
- Fsw =  ~450 KHz
- LAYOUT NOTE:
  Follow Layout Instructions guideline
